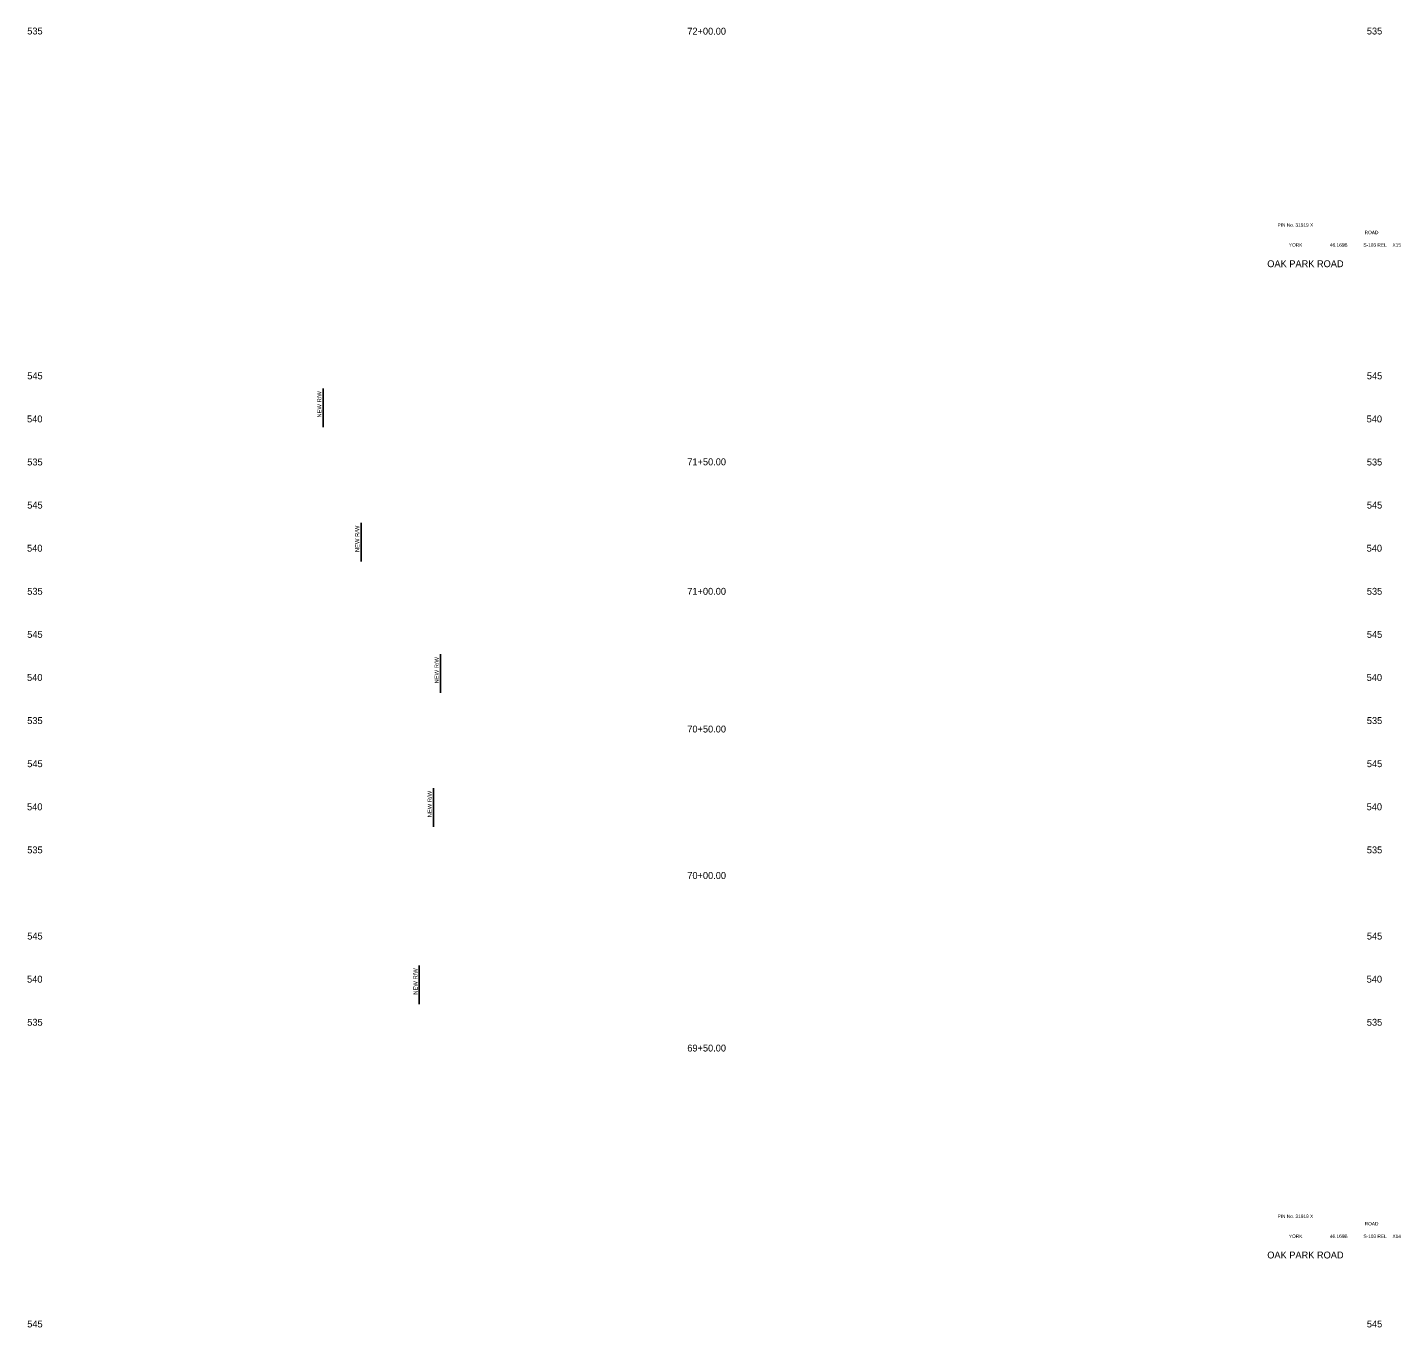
# Model space of a CAD drawing. Extents: x 1001 to 1161, y 1005 to 3518.
# Drawn here: x 1001.2 to 1160.6, y 2585.1 to 2735.9 of the extents above; entities that cross this region are included whole.
import ezdxf

# ---------------------------------------------------------------- set-up
doc = ezdxf.new("R2010")
doc.units = 0
for name, color, linetype in [('RD_SHT_TX', 7, 'Continuous'), ('RD_XS_NewRW', 7, 'Continuous'), ('RD_XS_TX_Elev_EX', 7, 'Continuous'), ('RD_XS_TX_Station', 7, 'Continuous')]:
    doc.layers.add(name, color=color, linetype=linetype)

msp = doc.modelspace()

# ---------------------------------------------------------------- linework, layer by layer
at = {"layer": 'RD_XS_NewRW'}
for p, q in [((1035.51, 2694.04), (1035.51, 2689.54)), ((1039.91, 2678.45), (1039.91, 2673.95)), ((1049.13, 2663.21), (1049.13, 2658.71)), ((1048.32, 2647.68), (1048.32, 2643.18)), ((1046.67, 2627.1), (1046.67, 2622.6))]:
    msp.add_line(p, q, dxfattribs=at)

# ---------------------------------------------------------------- texts
at = {"layer": 'RD_SHT_TX'}
for s, height, p in [('PIN No. 31919 X', 0.4, (1146.29, 2712.8)), ('ROAD', 0.4, (1156.41, 2711.93)), ('YORK', 0.4, (1147.61, 2710.48)), ('46.169B', 0.4, (1152.37, 2710.48)), ('S-103 REL', 0.4, (1156.26, 2710.48)), ('X15', 0.4, (1159.64, 2710.48)), ('OAK PARK ROAD', 0.8, (1145.1, 2708.1)), ('PIN No. 31919 X', 0.4, (1146.29, 2597.8)), ('ROAD', 0.4, (1156.41, 2596.93)), ('YORK', 0.4, (1147.61, 2595.48)), ('46.169B', 0.4, (1152.37, 2595.48)), ('S-103 REL', 0.4, (1156.26, 2595.48)), ('X14', 0.4, (1159.63, 2595.48)), ('OAK PARK ROAD', 0.8, (1145.1, 2593.1))]:
    msp.add_text(s, height=height, dxfattribs=at).set_placement(p)
at = {"layer": 'RD_XS_NewRW'}
for p in [(1035.31, 2690.65), (1039.71, 2675.05), (1048.93, 2659.81), (1048.12, 2644.28), (1046.47, 2623.7)]:
    msp.add_text('NEW R/W ', height=0.488, rotation=90, dxfattribs=at).set_placement(p)
at = {"layer": 'RD_XS_TX_Elev_EX'}
for s, p in [('535', (1001.16, 2735.1)), ('535', (1156.66, 2735.1)), ('545', (1001.16, 2695.1)), ('545', (1156.66, 2695.1)), ('540', (1001.14, 2690.1)), ('540', (1156.64, 2690.1)), ('535', (1001.16, 2685.1)), ('535', (1156.66, 2685.1)), ('545', (1001.16, 2680.1)), ('545', (1156.66, 2680.1)), ('540', (1001.14, 2675.1)), ('540', (1156.64, 2675.1)), ('535', (1001.16, 2670.1)), ('535', (1156.66, 2670.1)), ('545', (1001.16, 2665.1)), ('545', (1156.66, 2665.1)), ('540', (1001.14, 2660.1)), ('540', (1156.64, 2660.1)), ('535', (1001.16, 2655.1)), ('535', (1156.66, 2655.1)), ('545', (1001.16, 2650.1)), ('545', (1156.66, 2650.1)), ('540', (1001.14, 2645.1)), ('540', (1156.64, 2645.1)), ('535', (1001.16, 2640.1)), ('535', (1156.66, 2640.1)), ('545', (1001.16, 2630.1)), ('545', (1156.66, 2630.1)), ('540', (1001.14, 2625.1)), ('540', (1156.64, 2625.1)), ('535', (1001.16, 2620.1)), ('535', (1156.66, 2620.1)), ('545', (1001.16, 2585.1)), ('545', (1156.66, 2585.1))]:
    msp.add_text(s, height=0.8, dxfattribs=at).set_placement(p)
at = {"layer": 'RD_XS_TX_Station'}
for s, p in [('72+00.00', (1077.78, 2735.08)), ('71+50.00', (1077.78, 2685.12)), ('71+00.00', (1077.78, 2670.1)), ('70+50.00', (1077.78, 2654.12)), ('70+00.00', (1077.78, 2637.13)), ('69+50.00', (1077.78, 2617.11))]:
    msp.add_text(s, height=0.8, dxfattribs=at).set_placement(p)

doc.saveas('drawing.dxf')
